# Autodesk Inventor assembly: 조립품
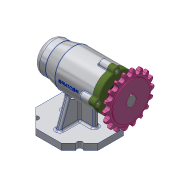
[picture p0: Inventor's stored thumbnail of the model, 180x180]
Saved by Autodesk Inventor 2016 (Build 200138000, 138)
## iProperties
Created: 2021-01
Part Number: 조립품
Document SubType Name: Assembly
Designer: MIRAE
Author: MIRAE
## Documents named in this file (12)
- C:\Users\MIRAE\Desktop\710106V1031\조립품.iam
- C:\Users\MIRAE\Desktop\710106V1031\본체.ipt
- C:\Users\MIRAE\Desktop\710106V1031\베어링 6004.ipt
- C:\Users\MIRAE\Desktop\710106V1031\축.ipt
- C:\Users\MIRAE\Desktop\710106V1031\커버.ipt
- C:\Users\MIRAE\Desktop\710106V1031\멈춤나사 M3.ipt
- C:\Users\MIRAE\Desktop\710106V1031\베어링 51202.ipt
- C:\Users\MIRAE\Desktop\710106V1031\어댑터슬리브.ipt
- C:\Users\MIRAE\Desktop\710106V1031\볼트 M4.ipt
- C:\Users\MIRAE\Desktop\710106V1031\스프로킷.ipt
- C:\Users\MIRAE\Desktop\710106V1031\키 5 x 5 x 14.ipt
- C:\Users\MIRAE\Desktop\710106V1031\오일 실.ipt
